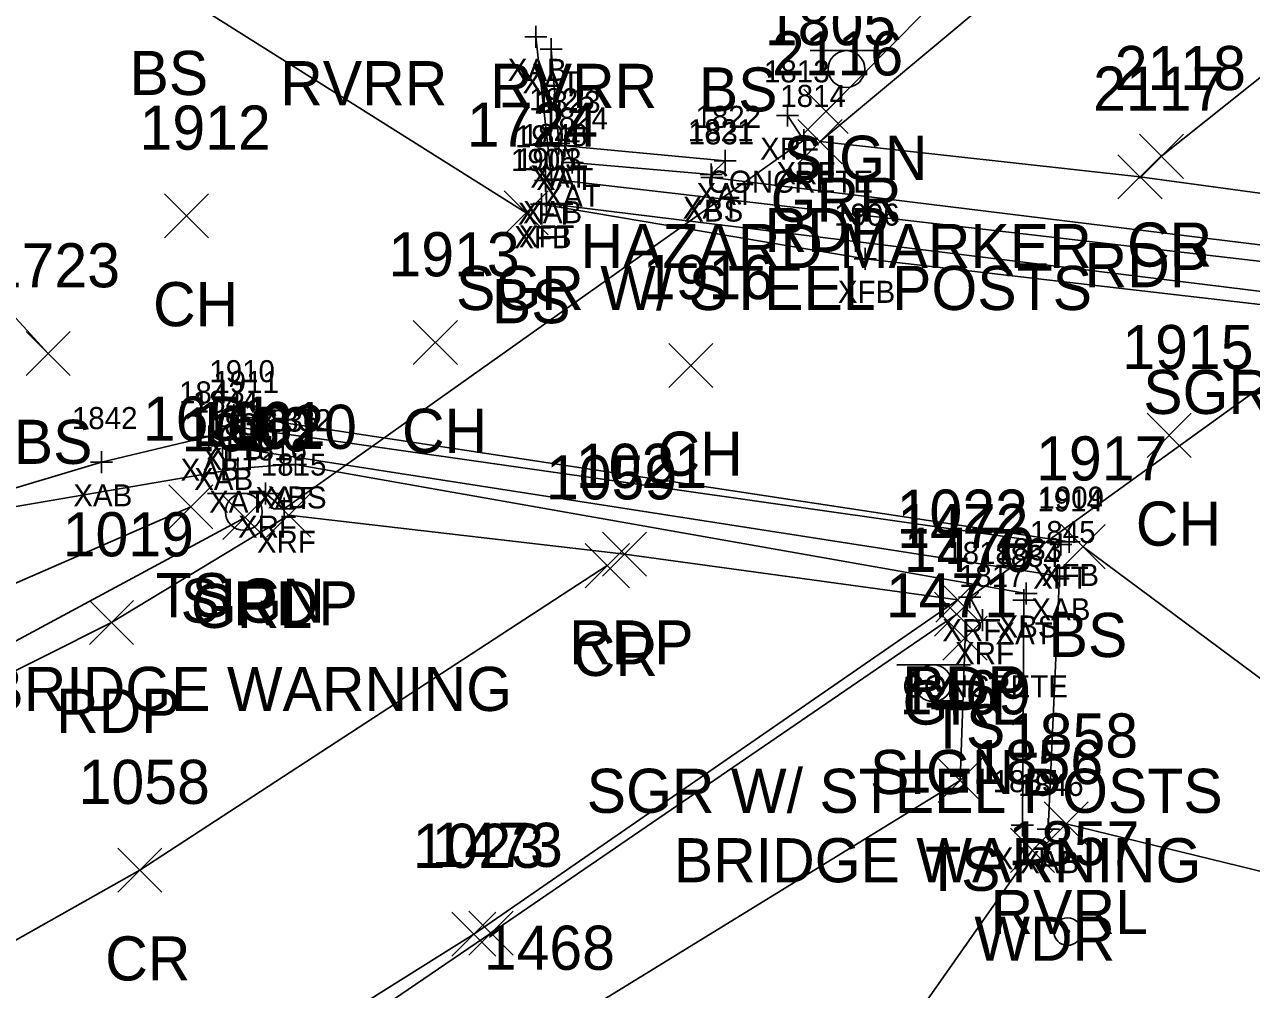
# Model space of a CAD drawing. Extents: x 1633660 to 1636532, y 388643 to 392631.
# Drawn here: x 1634438 to 1634493.7, y 388938.4 to 388982.1 of the extents above; entities that cross this region are included whole.
import ezdxf

# ---------------------------------------------------------------- set-up
doc = ezdxf.new("R2010")
doc.units = 0
for name, color, linetype in [('B_A', 7, 'Continuous'), ('B_C', 7, 'Continuous'), ('B_I', 7, 'Continuous'), ('B_TIC', 7, 'Continuous'), ('BFT', 7, 'Continuous'), ('BR', 7, 'Continuous'), ('BSE', 7, 'Continuous'), ('BSUBM', 7, 'Continuous'), ('L_A', 7, 'Continuous'), ('L_I', 7, 'Continuous'), ('L_TIC', 7, 'Continuous'), ('LAWA', 7, 'Continuous'), ('LAWE', 7, 'Continuous'), ('LELB', 7, 'Continuous'), ('M_I', 7, 'Continuous'), ('MPIP', 7, 'Continuous'), ('P_A', 7, 'Continuous'), ('P_I', 7, 'Continuous'), ('P_TIC', 7, 'Continuous'), ('PET', 7, 'Continuous'), ('PRC', 7, 'Continuous'), ('R_A', 7, 'Continuous'), ('R_C', 7, 'Continuous'), ('R_I', 7, 'Continuous'), ('R_TIC', 7, 'Continuous'), ('RGR', 7, 'Continuous'), ('S_A', 7, 'Continuous'), ('S_C', 7, 'Continuous'), ('S_I', 7, 'Continuous'), ('SSGN', 7, 'Continuous')]:
    doc.layers.add(name, color=color, linetype=linetype)

msp = doc.modelspace()

# ---------------------------------------------------------------- linework, layer by layer
at = {"layer": 'B_TIC'}
for p, q in [((1634461.231, 388981.527), (1634461.307, 388981.527)), ((1634461.918, 388980.965), (1634461.994, 388980.965)), ((1634472.631, 388977.96), (1634472.707, 388977.96)), ((1634462.269, 388976.696), (1634462.345, 388976.696)), ((1634462.535, 388976.58), (1634462.61, 388976.58)), ((1634473.371, 388976.847), (1634473.446, 388976.847)), ((1634462.868, 388975.826), (1634462.944, 388975.826)), ((1634469.809, 388975.899), (1634469.884, 388975.899)), ((1634469.181, 388975.288), (1634469.256, 388975.288)), ((1634461.666, 388975.012), (1634461.741, 388975.012)), ((1634461.93, 388975.078), (1634462.006, 388975.078)), ((1634469.211, 388975.152), (1634469.287, 388975.152)), ((1634461.486, 388973.946), (1634461.561, 388973.946)), ((1634461.71, 388973.979), (1634461.785, 388973.979)), ((1634476.157, 388971.469), (1634476.233, 388971.469)), ((1634447.532, 388964.374), (1634447.607, 388964.374)), ((1634447.386, 388963.89), (1634447.461, 388963.89)), ((1634446.399, 388963.412), (1634446.474, 388963.412)), ((1634447.018, 388962.993), (1634447.094, 388962.993)), ((1634441.539, 388962.249), (1634441.614, 388962.249)), ((1634447.712, 388961.965), (1634447.788, 388961.965)), ((1634449.806, 388962.133), (1634449.882, 388962.133)), ((1634450.326, 388962.153), (1634450.401, 388962.153)), ((1634448.965, 388960.83), (1634449.04, 388960.83)), ((1634449.821, 388960.144), (1634449.897, 388960.144)), ((1634485.399, 388958.644), (1634485.474, 388958.644)), ((1634485.024, 388958.521), (1634485.099, 388958.521)), ((1634484.971, 388957.086), (1634485.046, 388957.086)), ((1634480.894, 388956.138), (1634480.969, 388956.138)), ((1634483.353, 388956.001), (1634483.429, 388956.001)), ((1634483.458, 388956.306), (1634483.533, 388956.306)), ((1634481.469, 388955.096), (1634481.545, 388955.096)), ((1634483.28, 388945.797), (1634483.356, 388945.797)), ((1634484.459, 388945.628), (1634484.534, 388945.628))]:
    msp.add_line(p, q, dxfattribs=at)
for points in [[(1634461.228, 388981.027), (1634461.228, 388982.027)], [(1634460.728, 388981.527), (1634461.728, 388981.527)], [(1634461.915, 388980.465), (1634461.915, 388981.465)], [(1634461.415, 388980.965), (1634462.415, 388980.965)], [(1634472.628, 388977.46), (1634472.628, 388978.46)], [(1634472.128, 388977.96), (1634473.128, 388977.96)], [(1634462.266, 388976.196), (1634462.266, 388977.196)], [(1634462.531, 388976.08), (1634462.531, 388977.08)], [(1634473.367, 388976.347), (1634473.367, 388977.347)], [(1634461.766, 388976.696), (1634462.766, 388976.696)], [(1634462.031, 388976.58), (1634463.031, 388976.58)], [(1634469.805, 388975.399), (1634469.805, 388976.399)], [(1634472.867, 388976.847), (1634473.867, 388976.847)], [(1634462.365, 388975.826), (1634463.365, 388975.826)], [(1634462.865, 388975.326), (1634462.865, 388976.326)], [(1634469.305, 388975.899), (1634470.305, 388975.899)], [(1634461.662, 388974.512), (1634461.662, 388975.512)], [(1634461.927, 388974.578), (1634461.927, 388975.578)], [(1634468.677, 388975.288), (1634469.677, 388975.288)], [(1634469.177, 388974.788), (1634469.177, 388975.788)], [(1634469.208, 388974.652), (1634469.208, 388975.652)], [(1634461.162, 388975.012), (1634462.162, 388975.012)], [(1634461.427, 388975.078), (1634462.427, 388975.078)], [(1634468.708, 388975.152), (1634469.708, 388975.152)], [(1634461.482, 388973.446), (1634461.482, 388974.446)], [(1634461.706, 388973.479), (1634461.706, 388974.479)], [(1634460.982, 388973.946), (1634461.982, 388973.946)], [(1634461.206, 388973.979), (1634462.206, 388973.979)], [(1634476.154, 388970.969), (1634476.154, 388971.969)], [(1634475.654, 388971.469), (1634476.654, 388971.469)], [(1634447.528, 388963.874), (1634447.528, 388964.874)], [(1634447.028, 388964.374), (1634448.028, 388964.374)], [(1634447.382, 388963.39), (1634447.382, 388964.39)], [(1634446.395, 388962.912), (1634446.395, 388963.912)], [(1634446.882, 388963.89), (1634447.882, 388963.89)], [(1634445.895, 388963.412), (1634446.895, 388963.412)], [(1634447.015, 388962.493), (1634447.015, 388963.493)], [(1634441.535, 388961.749), (1634441.535, 388962.749)], [(1634446.515, 388962.993), (1634447.515, 388962.993)], [(1634449.803, 388961.633), (1634449.803, 388962.633)], [(1634450.322, 388961.653), (1634450.322, 388962.653)], [(1634441.035, 388962.249), (1634442.035, 388962.249)], [(1634447.209, 388961.965), (1634448.209, 388961.965)], [(1634447.709, 388961.465), (1634447.709, 388962.465)], [(1634449.303, 388962.133), (1634450.303, 388962.133)], [(1634449.822, 388962.153), (1634450.822, 388962.153)], [(1634448.461, 388960.83), (1634449.461, 388960.83)], [(1634448.961, 388960.33), (1634448.961, 388961.33)], [(1634449.818, 388959.644), (1634449.818, 388960.644)], [(1634449.318, 388960.144), (1634450.318, 388960.144)], [(1634485.395, 388958.144), (1634485.395, 388959.144)], [(1634484.895, 388958.644), (1634485.895, 388958.644)], [(1634485.02, 388958.021), (1634485.02, 388959.021)], [(1634484.52, 388958.521), (1634485.52, 388958.521)], [(1634484.967, 388956.586), (1634484.967, 388957.586)], [(1634484.467, 388957.086), (1634485.467, 388957.086)], [(1634480.89, 388955.638), (1634480.89, 388956.638)], [(1634483.35, 388955.501), (1634483.35, 388956.501)], [(1634483.454, 388955.806), (1634483.454, 388956.806)], [(1634480.39, 388956.138), (1634481.39, 388956.138)], [(1634482.85, 388956.001), (1634483.85, 388956.001)], [(1634482.954, 388956.306), (1634483.954, 388956.306)], [(1634481.466, 388954.596), (1634481.466, 388955.596)], [(1634480.966, 388955.096), (1634481.966, 388955.096)], [(1634482.777, 388945.797), (1634483.777, 388945.797)], [(1634483.277, 388945.297), (1634483.277, 388946.297)], [(1634484.455, 388945.128), (1634484.455, 388946.128)], [(1634483.955, 388945.628), (1634484.955, 388945.628)]]:
    msp.add_lwpolyline(points, dxfattribs=at)
at = {"layer": 'BFT'}
for points in [[(1634517.95, 388968.147), (1634504.943, 388968.654), (1634461.706, 388973.979), (1634461.662, 388975.012)], [(1634461.482, 388973.946), (1634476.154, 388971.469), (1634495.885, 388969.178), (1634517.986, 388967.785)], [(1634485.395, 388958.644), (1634447.528, 388964.374)], [(1634447.382, 388963.89), (1634485.02, 388958.521)]]:
    msp.add_lwpolyline(points, dxfattribs=at)
at = {"layer": 'BR'}
for points in [[(1634472.628, 388977.96), (1634473.367, 388976.847), (1634449.818, 388960.144), (1634448.961, 388960.83)], [(1634481.466, 388955.096), (1634480.89, 388956.138), (1634504.256, 388972.991), (1634504.99, 388972)]]:
    msp.add_lwpolyline(points, dxfattribs=at)
at = {"layer": 'BSE'}
for points in [[(1634504.002, 388970.876), (1634469.208, 388975.152)], [(1634450.322, 388962.153), (1634483.454, 388956.306)]]:
    msp.add_lwpolyline(points, dxfattribs=at)
at = {"layer": 'BSUBM'}
for points in [[(1634461.228, 388981.527), (1634461.927, 388975.078), (1634518.248, 388968.548), (1634518.851, 388970.092)], [(1634462.266, 388976.696), (1634461.915, 388980.965)], [(1634469.177, 388975.288), (1634469.805, 388975.899), (1634462.531, 388976.58), (1634462.865, 388975.826)], [(1634462.865, 388975.826), (1634469.177, 388975.288)], [(1634433.312, 388958.737), (1634436.128, 388960.642), (1634441.535, 388962.249), (1634446.395, 388963.412), (1634447.015, 388962.993), (1634484.967, 388957.086), (1634484.455, 388945.628)], [(1634449.803, 388962.133), (1634447.709, 388961.965), (1634435.881, 388959.935), (1634433.308, 388958.436)], [(1634483.35, 388956.001), (1634483.277, 388945.797)]]:
    msp.add_lwpolyline(points, dxfattribs=at)
at = {"layer": 'L_TIC'}
for points in [[(1634444.383, 388972.411), (1634446.383, 388974.411)], [(1634446.383, 388972.411), (1634444.383, 388974.411)], [(1634459.789, 388972.545), (1634461.789, 388974.545)], [(1634461.789, 388972.545), (1634459.789, 388974.545)], [(1634455.668, 388966.672), (1634457.668, 388968.672)], [(1634457.668, 388966.672), (1634455.668, 388968.672)], [(1634438.116, 388966.173), (1634440.116, 388968.173)], [(1634440.116, 388966.173), (1634438.116, 388968.173)], [(1634467.251, 388965.636), (1634469.251, 388967.636)], [(1634469.251, 388965.636), (1634467.251, 388967.636)], [(1634488.932, 388962.467), (1634490.932, 388964.467)], [(1634490.932, 388962.467), (1634488.932, 388964.467)], [(1634444.582, 388959.226), (1634446.582, 388961.226)], [(1634446.582, 388959.226), (1634444.582, 388961.226)], [(1634485.027, 388957.422), (1634487.027, 388959.422)], [(1634487.027, 388957.422), (1634485.027, 388959.422)], [(1634479.68, 388953.277), (1634481.68, 388955.277)], [(1634481.68, 388953.277), (1634479.68, 388955.277)], [(1634479.462, 388946.827), (1634481.462, 388948.827)], [(1634481.462, 388946.827), (1634479.462, 388948.827)], [(1634484.266, 388944.868), (1634486.266, 388946.868)], [(1634486.266, 388944.868), (1634484.266, 388946.868)], [(1634482.739, 388943.664), (1634484.739, 388945.664)], [(1634484.739, 388943.664), (1634482.739, 388945.664)]]:
    msp.add_lwpolyline(points, dxfattribs=at)
at = {"layer": 'LAWA'}
msp.add_lwpolyline([(1634130.811, 388762.968), (1634125.77, 388773.71), (1634128.727, 388780.906), (1634147.798, 388788.83), (1634164.313, 388795.201), (1634191.325, 388807.234), (1634212.876, 388815.093), (1634244.473, 388827.565), (1634270.045, 388838.562), (1634299.492, 388850.564), (1634310.774, 388855.38), (1634327.207, 388862.061), (1634379.707, 388881.611), (1634402.37, 388888.883), (1634424.472, 388897.455), (1634452.158, 388917.363), (1634475.032, 388932.291), (1634483.739, 388944.664)], dxfattribs=at)
at = {"layer": 'LAWE'}
msp.add_lwpolyline([(1634485.266, 388945.868), (1634504.196, 388941.237), (1634525.532, 388940.734), (1634548.507, 388932.941), (1634584.664, 388919.999), (1634598.752, 388914.409), (1634618.803, 388928.878), (1634638.301, 388944.913), (1634660.99, 388957.079), (1634677.576, 388983.238), (1634696.949, 389006.397), (1634707.364, 389033.308), (1634727.928, 389056.715), (1634749.887, 389078.696), (1634762.92, 389095.064), (1634797.897, 389102.54), (1634816.332, 389112.037), (1634824.178, 389130.773), (1634824.184, 389150.648), (1634818.446, 389174.952), (1634815.049, 389205.919), (1634802.108, 389220.823), (1634788.756, 389226.818)], dxfattribs=at)
at = {"layer": 'LELB'}
for points in [[(1634460.789, 388973.545), (1634444.362, 388983.888), (1634433.989, 389001.983), (1634424.839, 389019.55), (1634404.319, 389033.799), (1634375.922, 389039.907), (1634354.661, 389044.218), (1634353.99, 389044.472), (1634327.395, 389038.501), (1634309.253, 389034.477)], [(1634311.937, 389011.727), (1634343.3, 389019.171), (1634362.418, 389022.606), (1634391.71, 389019.285), (1634408.613, 389006.323), (1634418.168, 388990.077), (1634439.116, 388967.173)], [(1634445.582, 388960.226), (1634426.877, 388952.081), (1634393.484, 388937.195), (1634364.772, 388929.813), (1634350.49, 388919.544), (1634324.395, 388908.277), (1634285.496, 388891.779), (1634241.121, 388873.713), (1634233.64, 388876.293)], [(1634486.027, 388958.422), (1634504.065, 388945.032), (1634527.825, 388945.016), (1634547.828, 388937.523), (1634559.739, 388934.65), (1634574.188, 388927.827), (1634589.055, 388923.965), (1634604.769, 388924.757), (1634617.827, 388931.522), (1634629.874, 388942.081)], [(1634125.579, 388742.686), (1634122.377, 388746.523), (1634122.379, 388759.174), (1634119.847, 388773.411), (1634127.606, 388794.705), (1634159.932, 388808.1), (1634199.649, 388823.276), (1634240.013, 388839.132), (1634282.637, 388856.778), (1634322.867, 388872.904), (1634357.402, 388883.596), (1634392.968, 388895.749), (1634413.992, 388898.724), (1634440.42, 388919.1), (1634461.601, 388936.25), (1634480.462, 388947.827), (1634480.68, 388954.277)]]:
    msp.add_lwpolyline(points, dxfattribs=at)
at = {"layer": 'MPIP'}
for radius in [0.625, 0.0833]:
    msp.add_circle((1634485.329, 388940.983), radius, dxfattribs=at)
at = {"layer": 'P_TIC'}
for points in [[(1634473.107, 388975.774), (1634475.107, 388977.774)], [(1634475.107, 388975.774), (1634473.107, 388977.774)], [(1634488.589, 388975.111), (1634490.589, 388977.111)], [(1634490.589, 388975.111), (1634488.589, 388977.111)], [(1634487.61, 388974.178), (1634489.61, 388976.178)], [(1634489.61, 388974.178), (1634487.61, 388976.178)], [(1634449.019, 388958.853), (1634451.019, 388960.853)], [(1634451.019, 388958.853), (1634449.019, 388960.853)], [(1634464.24, 388957.085), (1634466.24, 388959.085)], [(1634466.24, 388957.085), (1634464.24, 388959.085)], [(1634463.462, 388956.565), (1634465.462, 388958.565)], [(1634465.462, 388956.565), (1634463.462, 388958.565)], [(1634479.348, 388955.008), (1634481.348, 388957.008)], [(1634481.348, 388955.008), (1634479.348, 388957.008)], [(1634440.986, 388953.985), (1634442.986, 388955.985)], [(1634442.986, 388953.985), (1634440.986, 388955.985)], [(1634442.268, 388942.766), (1634444.268, 388944.766)], [(1634444.268, 388942.766), (1634442.268, 388944.766)], [(1634457.413, 388939.869), (1634459.413, 388941.869)], [(1634459.413, 388939.869), (1634457.413, 388941.869)]]:
    msp.add_lwpolyline(points, dxfattribs=at)
at = {"layer": 'PET'}
for points in [[(1634682.082, 389181.099), (1634650.696, 389146.378), (1634620.246, 389115.231), (1634604.629, 389098.298), (1634579.097, 389070.12), (1634546.556, 389039.303), (1634509.68, 389006.458), (1634474.107, 388976.774), (1634488.61, 388975.178), (1634504.361, 388973.036), (1634532.027, 388994.362), (1634563.211, 389020.041), (1634596.335, 389051.022), (1634641.933, 389096.55), (1634679.614, 389135.055), (1634705.94, 389161.603), (1634722.451, 389175.585), (1634749.297, 389203.848), (1634763.452, 389218.449), (1634753.185, 389229.521), (1634742.756, 389239.644), (1634704.358, 389200.187), (1634691.629, 389189.006)], [(1634182.589, 388846.73), (1634235.607, 388867.857), (1634289.807, 388889.547), (1634340.226, 388910.316), (1634383.943, 388928.36), (1634416.956, 388942.424), (1634441.986, 388954.985), (1634450.019, 388959.853), (1634465.24, 388958.085), (1634480.348, 388956.008), (1634458.413, 388940.869), (1634427.909, 388921.751), (1634384.731, 388901.048), (1634334.49, 388879.365), (1634279.866, 388857.153), (1634233.656, 388838.288), (1634176.136, 388816.11)]]:
    msp.add_lwpolyline(points, dxfattribs=at)
at = {"layer": 'PRC'}
for points in [[(1634489.589, 388976.111), (1634524.497, 389003.937), (1634553.651, 389029.267), (1634589.65, 389062.971), (1634628.748, 389101.269), (1634671.28, 389144.583), (1634699.51, 389173.358), (1634712.637, 389186.748), (1634739.317, 389214.16), (1634752.843, 389228.985)], [(1633685.214, 388740.891), (1633722.466, 388753.089), (1633765.947, 388761.743), (1633808.839, 388766.445), (1633860.632, 388768.049), (1633911.929, 388769.082), (1633965.446, 388772.582), (1634019.676, 388781.056), (1634071.374, 388793.875), (1634111.14, 388806.365), (1634160.922, 388824.059), (1634207.926, 388842.024), (1634253.706, 388860.359), (1634302.739, 388880.25), (1634347.864, 388899.141), (1634390.053, 388916.892), (1634425.595, 388933.799), (1634443.268, 388943.766), (1634464.462, 388957.565)]]:
    msp.add_lwpolyline(points, dxfattribs=at)
at = {"layer": 'R_TIC'}
for points in [[(1634473.377, 388977.145), (1634475.377, 388979.145)], [(1634475.377, 388977.145), (1634473.377, 388979.145)], [(1634447.041, 388958.741), (1634449.041, 388960.741)], [(1634449.041, 388958.741), (1634447.041, 388960.741)], [(1634479.3, 388954.361), (1634481.3, 388956.361)], [(1634481.3, 388954.361), (1634479.3, 388956.361)], [(1634458.19, 388939.913), (1634460.19, 388941.913)], [(1634460.19, 388939.913), (1634458.19, 388941.913)]]:
    msp.add_lwpolyline(points, dxfattribs=at)
at = {"layer": 'RGR'}
for points in [[(1634500.902, 389005.756), (1634487.765, 388991.671), (1634474.377, 388978.145)], [(1634366.612, 388925.989), (1634383.781, 388928.869), (1634397.708, 388935.211), (1634426.027, 388947.9), (1634448.041, 388959.741)], [(1634480.3, 388955.361), (1634459.19, 388940.913), (1634428.243, 388919.846), (1634416.071, 388910.226), (1634409.286, 388902.118)]]:
    msp.add_lwpolyline(points, dxfattribs=at)
at = {"layer": 'SSGN'}
for p, q in [((1634473.655, 388980.898), (1634476.989, 388980.898)), ((1634475.302, 388980.064), (1634475.302, 388980.064)), ((1634446.335, 388960.832), (1634449.669, 388960.832)), ((1634447.982, 388959.999), (1634447.982, 388959.999)), ((1634477.588, 388953.068), (1634480.921, 388953.068)), ((1634479.235, 388952.235), (1634479.235, 388952.235))]:
    msp.add_line(p, q, dxfattribs=at)
for centre in [(1634475.302, 388980.064), (1634447.982, 388959.999), (1634479.235, 388952.235)]:
    msp.add_circle(centre, 0.833, dxfattribs=at)

# ---------------------------------------------------------------- texts
at = {"layer": 'B_A'}
for s, p in [('XAB', (1634459.948, 388979.527)), ('XAT', (1634460.619, 388978.965)), ('XRF', (1634471.388, 388975.96)), ('XRF', (1634472.127, 388974.847)), ('XAT', (1634460.971, 388974.696)), ('XAT', (1634461.236, 388974.58)), ('XAT', (1634461.569, 388973.826)), ('XAT', (1634468.51, 388973.899)), ('XAT', (1634467.882, 388973.288)), ('XBS', (1634467.948, 388973.152)), ('XFT', (1634460.406, 388973.012)), ('XAB', (1634460.647, 388973.078)), ('XFB', (1634460.242, 388971.946)), ('XFT', (1634460.45, 388971.979)), ('XFB', (1634474.913, 388969.469)), ('XFB', (1634446.288, 388962.374)), ('XFT', (1634446.126, 388961.89)), ('XAB', (1634445.116, 388961.412)), ('XAB', (1634445.735, 388960.993)), ('XAB', (1634440.256, 388960.249)), ('XAT', (1634446.413, 388959.965)), ('XAT', (1634448.507, 388960.133)), ('XBS', (1634449.063, 388960.153)), ('XRF', (1634447.721, 388958.83)), ('XRF', (1634448.577, 388958.144)), ('XFT', (1634483.764, 388956.521)), ('XFB', (1634484.155, 388956.644)), ('XAB', (1634483.688, 388955.086)), ('XBS', (1634482.194, 388954.306)), ('XRF', (1634479.65, 388954.138)), ('XAT', (1634482.055, 388954.001)), ('XRF', (1634480.226, 388953.096)), ('XAT', (1634481.981, 388943.797)), ('XAB', (1634483.176, 388943.628))]:
    msp.add_text(s, height=1, dxfattribs=at).set_placement(p)
at = {"layer": 'B_C'}
for p in [(1634469.006, 388974.46), (1634477.844, 388951.596)]:
    msp.add_text('CONCRETE', height=1, dxfattribs=at).set_placement(p)
at = {"layer": 'B_I'}
for s, p in [('1813', (1634471.565, 388979.46)), ('1825', (1634460.919, 388978.196)), ('1814', (1634472.304, 388978.347)), ('1823', (1634461.185, 388978.08)), ('1824', (1634461.518, 388977.326)), ('1822', (1634468.459, 388977.399)), ('1904', (1634460.276, 388976.512)), ('1848', (1634460.58, 388976.578)), ('1821', (1634468.114, 388976.788)), ('1831', (1634468.145, 388976.652)), ('1905', (1634460.096, 388975.446)), ('1903', (1634460.32, 388975.479)), ('1906', (1634474.74, 388972.969)), ('1910', (1634446.422, 388965.874)), ('1911', (1634446.603, 388965.39)), ('1843', (1634445.049, 388964.912)), ('1844', (1634445.668, 388964.493)), ('1842', (1634440.189, 388963.749)), ('1837', (1634446.362, 388963.465)), ('1836', (1634448.429, 388963.633)), ('1832', (1634448.976, 388963.653)), ('1816', (1634447.871, 388962.33)), ('1815', (1634448.755, 388961.644)), ('1914', (1634483.957, 388960.021)), ('1909', (1634484.005, 388960.144)), ('1845', (1634483.621, 388958.586)), ('1818', (1634479.827, 388957.638)), ('1833', (1634482.108, 388957.806)), ('1834', (1634482.003, 388957.501)), ('1817', (1634480.403, 388956.596)), ('1835', (1634481.93, 388947.297)), ('1846', (1634483.081, 388947.128))]:
    msp.add_text(s, height=1, dxfattribs=at).set_placement(p)
at = {"layer": 'L_A'}
for s, p in [('BS', (1634442.803, 388978.888)), ('RVRR', (1634449.633, 388978.424)), ('RVRR', (1634459.148, 388978.301)), ('BS', (1634468.612, 388978.139)), ('CH', (1634443.871, 388968.411)), ('BS', (1634459.23, 388968.545)), ('CH', (1634455.156, 388962.672)), ('BS', (1634437.557, 388962.173)), ('CH', (1634466.739, 388961.636)), ('CH', (1634488.42, 388958.467)), ('TS', (1634443.992, 388955.226)), ('BS', (1634484.468, 388953.422)), ('TS', (1634479.089, 388949.277)), ('TS', (1634478.871, 388942.827)), ('RVRL', (1634481.833, 388940.868)), ('WDR', (1634481.101, 388939.664))]:
    msp.add_text(s, height=2, dxfattribs=at).set_placement(p)
at = {"layer": 'L_I'}
for s, p in [('1912', (1634443.257, 388976.411)), ('1724', (1634458.096, 388976.545)), ('1913', (1634454.542, 388970.672)), ('1723', (1634436.423, 388970.173)), ('1916', (1634466.07, 388969.636)), ('1915', (1634487.806, 388966.467)), ('1651', (1634443.409, 388963.226)), ('1917', (1634483.901, 388961.422)), ('1470', (1634477.9, 388957.277)), ('1469', (1634477.714, 388950.827)), ('1858', (1634482.574, 388948.868)), ('1856', (1634480.991, 388947.664)), ('1468', (1634458.861, 388939.25))]:
    msp.add_text(s, height=2, dxfattribs=at).set_placement(p)
at = {"layer": 'M_I'}
msp.add_text('1857', height=2, dxfattribs=at).set_placement((1634482.636, 388943.983))
at = {"layer": 'P_A'}
for s, p in [('RDP', (1634471.595, 388971.774)), ('CR', (1634488.022, 388971.111)), ('RDP', (1634486.098, 388970.178)), ('RDP', (1634447.507, 388954.853)), ('RDP', (1634462.728, 388953.085)), ('CR', (1634462.895, 388952.565)), ('RDP', (1634477.836, 388951.008)), ('RDP', (1634439.474, 388949.985)), ('CR', (1634441.701, 388938.766))]:
    msp.add_text(s, height=2, dxfattribs=at).set_placement(p)
at = {"layer": 'P_I'}
for s, p in [('2116', (1634471.926, 388979.774)), ('2118', (1634487.463, 388979.111)), ('2117', (1634486.484, 388978.178)), ('1020', (1634447.16, 388962.853)), ('1021', (1634463.035, 388961.085)), ('1059', (1634461.683, 388960.565)), ('1022', (1634477.576, 388959.008)), ('1019', (1634439.774, 388957.985)), ('1058', (1634440.496, 388946.766)), ('1023', (1634455.642, 388943.869))]:
    msp.add_text(s, height=2, dxfattribs=at).set_placement(p)
at = {"layer": 'R_A'}
for s, p in [('GRR', (1634471.866, 388973.145)), ('GRL', (1634445.584, 388954.741)), ('GRL', (1634477.843, 388950.361))]:
    msp.add_text(s, height=2, dxfattribs=at).set_placement(p)
at = {"layer": 'R_C'}
for p in [(1634457.606, 388969.145), (1634488.757, 388964.436), (1634463.528, 388946.361)]:
    msp.add_text('SGR W/ STEEL POSTS', height=2, dxfattribs=at).set_placement(p)
at = {"layer": 'R_I'}
for s, p in [('1805', (1634471.606, 388981.145)), ('1660', (1634445.167, 388962.741)), ('1472', (1634477.607, 388958.361)), ('1473', (1634456.497, 388943.913))]:
    msp.add_text(s, height=2, dxfattribs=at).set_placement(p)
at = {"layer": 'S_A'}
for p in [(1634472.44, 388975.044), (1634445.12, 388954.978), (1634476.373, 388947.215)]:
    msp.add_text('SIGN', height=2, dxfattribs=at).set_placement(p)
at = {"layer": 'S_C'}
for s, p in [('HAZARD MARKER', (1634463.243, 388971.044)), ('BRIDGE WARNING', (1634436.222, 388950.978)), ('BRIDGE WARNING', (1634467.475, 388943.215))]:
    msp.add_text(s, height=2, dxfattribs=at).set_placement(p)
at = {"layer": 'S_I'}
for s, p in [('1661', (1634445.742, 388962.978)), ('1471', (1634477.089, 388955.215))]:
    msp.add_text(s, height=2, dxfattribs=at).set_placement(p)

doc.saveas('drawing.dxf')
